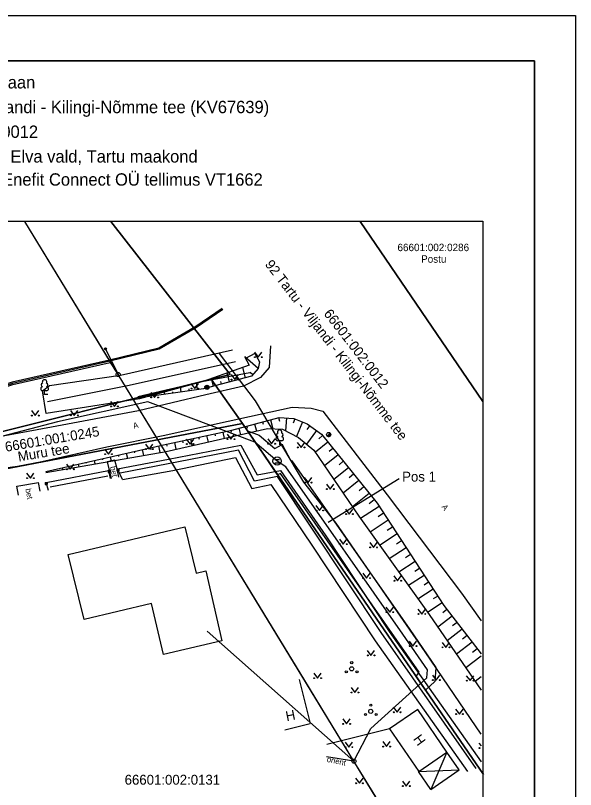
# Model space of a CAD drawing. Extents: x 627624 to 627729, y 6468528 to 6468676.
# Drawn here: x 627660.6 to 627728.6, y 6468582.3 to 6468676.3 of the extents above; entities that cross this region are included whole.
import ezdxf

# ---------------------------------------------------------------- set-up
doc = ezdxf.new("R2010")
doc.units = 0
for name, color, linetype in [('AED', 7, 'Continuous'), ('HALJASTUS', 7, 'Continuous'), ('HOONE', 7, 'Continuous'), ('Hoone Elu- või ühiskondlik hoone', 7, 'Continuous'), ('HOONEDET', 7, 'Continuous'), ('KASUTUSALA', 7, 'Continuous'), ('KPKAABEL', 7, 'Continuous'), ('MPKAABEL', 7, 'Continuous'), ('MPOHULIIN', 7, 'Continuous'), ('PIIR', 7, 'Continuous'), ('POST', 7, 'Continuous'), ('PR_SIDE', 7, 'Continuous'), ('proj_trass_kliendiliin ohuliin', 7, 'Continuous'), ('proj_trass_multitoru ohuliinil', 7, 'Continuous'), ('PUU', 7, 'Continuous'), ('RAJATIS', 7, 'Continuous'), ('RELJEEF', 7, 'Continuous'), ('SITRASS', 7, 'Continuous'), ('TEE', 7, 'Continuous'), ('VORMISTUS', 7, 'Continuous')]:
    doc.layers.add(name, color=color, linetype=linetype)

msp = doc.modelspace()

# ---------------------------------------------------------------- linework, layer by layer
at = {"layer": 'AED'}
for p, q in [((627671.829, 6468621.099), (627671.829, 6468620.849)), ((627671.829, 6468621.099), (627672.079, 6468621.099)), ((627671.829, 6468620.849), (627672.079, 6468620.849)), ((627672.079, 6468621.099), (627672.079, 6468620.849)), ((627672.91, 6468621.284), (627672.91, 6468621.034)), ((627672.91, 6468621.284), (627673.16, 6468621.284)), ((627672.91, 6468621.034), (627673.16, 6468621.034)), ((627673.16, 6468621.284), (627673.16, 6468621.034)), ((627664.186, 6468619.637), (627664.186, 6468619.387)), ((627664.186, 6468619.637), (627664.436, 6468619.637)), ((627664.436, 6468619.637), (627664.436, 6468619.387)), ((627664.186, 6468619.387), (627664.436, 6468619.387)), ((627706.037, 6468589.677), (627698.423, 6468587.794))]:
    msp.add_line(p, q, dxfattribs=at)
at = {"layer": 'HALJASTUS'}
for p, q in [((627689.619, 6468635.444), (627690.082, 6468634.837)), ((627690.082, 6468634.837), (627690.528, 6468635.444)), ((627686.777, 6468632.723), (627687.24, 6468632.116)), ((627687.24, 6468632.116), (627687.686, 6468632.723)), ((627681.896, 6468631.637), (627682.36, 6468631.031)), ((627682.36, 6468631.031), (627682.805, 6468631.637)), ((627677.016, 6468630.552), (627677.479, 6468629.945)), ((627677.479, 6468629.945), (627677.925, 6468630.552)), ((627672.135, 6468629.466), (627672.598, 6468628.86)), ((627672.598, 6468628.86), (627673.044, 6468629.466)), ((627662.515, 6468628.343), (627662.979, 6468627.737)), ((627662.979, 6468627.737), (627663.424, 6468628.343)), ((627667.254, 6468628.381), (627667.717, 6468627.774)), ((627667.717, 6468627.774), (627668.163, 6468628.381)), ((627686.303, 6468625.491), (627686.767, 6468624.885)), ((627686.767, 6468624.885), (627687.212, 6468625.491)), ((627676.376, 6468624.287), (627676.84, 6468623.68)), ((627676.84, 6468623.68), (627677.285, 6468624.287)), ((627681.34, 6468624.889), (627681.803, 6468624.282)), ((627681.803, 6468624.282), (627682.249, 6468624.889)), ((627691.237, 6468624.939), (627691.701, 6468624.332)), ((627691.701, 6468624.332), (627692.146, 6468624.939)), ((627694.818, 6468624.487), (627695.282, 6468623.88)), ((627695.282, 6468623.88), (627695.727, 6468624.487)), ((627671.416, 6468623.671), (627671.88, 6468623.064)), ((627671.88, 6468623.064), (627672.325, 6468623.671)), ((627666.768, 6468621.827), (627667.232, 6468621.22)), ((627667.232, 6468621.22), (627667.677, 6468621.827)), ((627661.927, 6468620.755), (627662.391, 6468620.148)), ((627662.391, 6468620.148), (627662.836, 6468620.755)), ((627664.781, 6468619.103), (627671.798, 6468620.423)), ((627695.682, 6468620.217), (627696.146, 6468619.61)), ((627696.146, 6468619.61), (627696.591, 6468620.217)), ((627698.368, 6468619.424), (627698.831, 6468618.817)), ((627698.831, 6468618.817), (627699.277, 6468619.424)), ((627697.083, 6468616.826), (627697.547, 6468616.219)), ((627697.547, 6468616.219), (627697.992, 6468616.826)), ((627700.689, 6468616.392), (627701.153, 6468615.785)), ((627701.153, 6468615.785), (627701.598, 6468616.392)), ((627699.95, 6468612.729), (627700.413, 6468612.123)), ((627700.413, 6468612.123), (627700.859, 6468612.729)), ((627703.625, 6468612.345), (627704.088, 6468611.738)), ((627704.088, 6468611.738), (627704.534, 6468612.345)), ((627702.774, 6468608.603), (627703.237, 6468607.996)), ((627703.237, 6468607.996), (627703.683, 6468608.603)), ((627706.56, 6468608.297), (627707.024, 6468607.69)), ((627707.024, 6468607.69), (627707.469, 6468608.297)), ((627705.598, 6468604.477), (627706.061, 6468603.87)), ((627706.061, 6468603.87), (627706.507, 6468604.477)), ((627709.496, 6468604.249), (627709.959, 6468603.643)), ((627709.959, 6468603.643), (627710.405, 6468604.249)), ((627708.421, 6468600.351), (627708.885, 6468599.744)), ((627708.885, 6468599.744), (627709.33, 6468600.351)), ((627712.431, 6468600.202), (627712.895, 6468599.595)), ((627712.895, 6468599.595), (627713.34, 6468600.202)), ((627703.321, 6468599.226), (627703.784, 6468598.619)), ((627703.784, 6468598.619), (627704.23, 6468599.226)), ((627696.823, 6468596.463), (627697.286, 6468595.856)), ((627697.286, 6468595.856), (627697.732, 6468596.463)), ((627711.245, 6468596.224), (627711.709, 6468595.618)), ((627711.709, 6468595.618), (627712.154, 6468596.224)), ((627715.367, 6468596.154), (627715.83, 6468595.548)), ((627715.83, 6468595.548), (627716.276, 6468596.154)), ((627701.368, 6468594.711), (627701.831, 6468594.104)), ((627701.831, 6468594.104), (627702.277, 6468594.711)), ((627706.485, 6468592.319), (627706.949, 6468591.712)), ((627706.949, 6468591.712), (627707.394, 6468592.319)), ((627714.069, 6468592.098), (627714.533, 6468591.491)), ((627714.533, 6468591.491), (627714.978, 6468592.098)), ((627700.358, 6468590.904), (627700.821, 6468590.297)), ((627700.821, 6468590.297), (627701.267, 6468590.904)), ((627700.627, 6468588.074), (627701.091, 6468587.467)), ((627701.091, 6468587.467), (627701.536, 6468588.074)), ((627705.206, 6468588.141), (627705.669, 6468587.534)), ((627705.669, 6468587.534), (627706.115, 6468588.141)), ((627716.893, 6468587.972), (627717.167, 6468587.613)), ((627701.907, 6468583.694), (627702.37, 6468583.087)), ((627702.37, 6468583.087), (627702.816, 6468583.694)), ((627707.596, 6468583.357), (627708.06, 6468582.75)), ((627708.06, 6468582.75), (627708.505, 6468583.357))]:
    msp.add_line(p, q, dxfattribs=at)
for points in [[(627664.314, 6468627.994), (627663.863, 6468630.771), (627664.725, 6468631.383), (627673.353, 6468632.664), (627686.946, 6468635.712)], [(627664.47, 6468629.471), (627674.392, 6468631.453), (627687.331, 6468634.332)], [(627689.052, 6468632.927), (627683.236, 6468631.825), (627675.654, 6468629.762), (627664.314, 6468627.994)], [(627673.61, 6468619.969), (627672.976, 6468621.286), (627679.187, 6468622.456), (627687.969, 6468624.157), (627689.948, 6468620.551), (627692.796, 6468621.064), (627698.292, 6468613.159), (627705.989, 6468601.538), (627717.166, 6468585.678)], [(627716.572, 6468584.873), (627705.028, 6468601.396), (627692.406, 6468620.356), (627689.621, 6468619.759), (627687.703, 6468623.543), (627673.321, 6468620.739)], [(627673.61, 6468619.969), (627679.701, 6468621.092), (627687.315, 6468622.642), (627689.297, 6468618.889), (627691.61, 6468619.392), (627696.609, 6468612.017), (627704.309, 6468600.39), (627715.503, 6468584.506)], [(627664.609, 6468618.629), (627664.298, 6468619.611), (627671.869, 6468621.074), (627672.073, 6468620.112)]]:
    msp.add_lwpolyline(points, dxfattribs=at)
for centre in [(627689.681, 6468634.837), (627690.51, 6468634.837), (627686.839, 6468632.116), (627687.668, 6468632.116), (627681.959, 6468631.031), (627682.787, 6468631.031), (627677.078, 6468629.945), (627677.907, 6468629.945), (627672.197, 6468628.86), (627673.026, 6468628.86), (627662.578, 6468627.737), (627663.407, 6468627.737), (627667.316, 6468627.774), (627668.145, 6468627.774), (627681.402, 6468624.282), (627682.231, 6468624.282), (627686.366, 6468624.885), (627687.195, 6468624.885), (627691.3, 6468624.332), (627692.129, 6468624.332), (627676.439, 6468623.68), (627677.267, 6468623.68), (627694.881, 6468623.88), (627695.709, 6468623.88), (627671.479, 6468623.064), (627672.307, 6468623.064), (627666.831, 6468621.22), (627667.66, 6468621.22), (627661.99, 6468620.148), (627662.819, 6468620.148), (627695.745, 6468619.61), (627696.573, 6468619.61), (627698.43, 6468618.817), (627699.259, 6468618.817), (627697.146, 6468616.219), (627697.975, 6468616.219), (627700.752, 6468615.785), (627701.58, 6468615.785), (627700.012, 6468612.123), (627700.841, 6468612.123), (627703.687, 6468611.738), (627704.516, 6468611.738), (627702.836, 6468607.996), (627703.665, 6468607.996), (627706.623, 6468607.69), (627707.451, 6468607.69), (627705.66, 6468603.87), (627706.489, 6468603.87), (627709.558, 6468603.643), (627710.387, 6468603.643), (627708.484, 6468599.744), (627709.313, 6468599.744), (627712.494, 6468599.595), (627713.323, 6468599.595), (627703.383, 6468598.619), (627704.212, 6468598.619), (627696.885, 6468595.856), (627697.714, 6468595.856), (627711.308, 6468595.618), (627712.137, 6468595.618), (627715.429, 6468595.548), (627716.258, 6468595.548), (627701.43, 6468594.104), (627702.259, 6468594.104), (627706.548, 6468591.712), (627707.377, 6468591.712), (627714.132, 6468591.491), (627714.96, 6468591.491), (627700.42, 6468590.297), (627701.249, 6468590.297), (627705.268, 6468587.534), (627706.097, 6468587.534), (627700.69, 6468587.467), (627701.518, 6468587.467), (627716.955, 6468587.365), (627701.969, 6468583.087), (627702.798, 6468583.087), (627707.659, 6468582.75), (627708.488, 6468582.75)]:
    msp.add_circle(centre, 0.055, dxfattribs=at)
at = {"layer": 'HOONE'}
for p, q in [((627695.051, 6468595.673), (627696.376, 6468590.356)), ((627693.298, 6468589.589), (627696.386, 6468590.358)), ((627714.488, 6468584.702), (627713.001, 6468586.862)), ((627711.065, 6468582.328), (627709.57, 6468584.502)), ((627711.065, 6468582.328), (627714.488, 6468584.702))]:
    msp.add_line(p, q, dxfattribs=at)
msp.add_lwpolyline([(627706.037, 6468589.677), (627709.589, 6468584.515), (627713.017, 6468586.873), (627709.466, 6468592.035)], close=True, dxfattribs=at)
at = {"layer": 'Hoone Elu- või ühiskondlik hoone'}
msp.add_lwpolyline([(627678.585, 6468598.716), (627677.114, 6468604.925), (627668.925, 6468602.995), (627666.971, 6468610.855), (627681.171, 6468614.225), (627682.555, 6468608.606), (627683.705, 6468608.876), (627685.675, 6468600.395)], close=True, dxfattribs=at)
at = {"layer": 'HOONEDET'}
for p, q in [((627713.001, 6468586.862), (627711.065, 6468582.328)), ((627709.57, 6468584.502), (627714.488, 6468584.702))]:
    msp.add_line(p, q, dxfattribs=at)
at = {"layer": 'KASUTUSALA'}
msp.add_lwpolyline([(627688.77, 6468625.91), (627690.186, 6468625.375), (627692.094, 6468623.767), (627693.002, 6468624.248), (627694.016, 6468622.332), (627694.153, 6468622.241), (627708.491, 6468601.771), (627711.663, 6468597.152), (627711.557, 6468595.436), (627710.406, 6468594.398), (627709.264, 6468596.061), (627709.624, 6468596.588), (627692.769, 6468620.73), (627692.444, 6468620.559), (627690.735, 6468623.048)], close=True, dxfattribs=at)
at = {"layer": 'KPKAABEL'}
msp.add_lwpolyline([(627685.782, 6468640.643), (627682.599, 6468638.441), (627678.043, 6468635.809), (627672.046, 6468634.344), (627660.214, 6468631.662), (627657.997, 6468630.954), (627658.117, 6468626.708), (627657.689, 6468626.13), (627652.495, 6468625.008), (627640.455, 6468623.259), (627634.742, 6468622.776)], dxfattribs=at)
at = {"layer": 'MPKAABEL'}
msp.add_line((627701.716, 6468585.772), (627698.369, 6468586.307), dxfattribs=at)
for points in [[(627685.699, 6468640.768), (627682.519, 6468638.568), (627677.987, 6468635.95), (627672.012, 6468634.49), (627660.175, 6468631.807), (627657.844, 6468631.063), (627657.966, 6468626.756), (627657.602, 6468626.265), (627652.468, 6468625.156), (627640.438, 6468623.408), (627634.759, 6468622.928)], [(627634.732, 6468622.624), (627640.472, 6468623.11), (627652.522, 6468624.86), (627657.776, 6468625.995), (627658.268, 6468626.66), (627658.15, 6468630.845), (627660.253, 6468631.517), (627672.08, 6468634.198), (627673.058, 6468632.736)]]:
    msp.add_lwpolyline(points, dxfattribs=at)
at = {"layer": 'MPOHULIIN'}
for points in [[(627672.71, 6468633.307), (627661.72, 6468651.3)], [(627679.915, 6468621.5), (627673.058, 6468632.736), (627672.71, 6468633.307)], [(627695.728, 6468595.585), (627679.915, 6468621.5)], [(627704.355, 6468581.436), (627701.716, 6468585.772), (627695.728, 6468595.585)]]:
    msp.add_lwpolyline(points, dxfattribs=at)
at = {"layer": 'PIIR'}
for points in [[(627672.184, 6468651.3), (627686.69, 6468632.75), (627684.35, 6468632.16), (627652.69, 6468624.22), (627634.665, 6468622.433)], [(627717.444, 6468584.146), (627688.18, 6468626.77), (627684.35, 6468632.16), (627686.69, 6468632.75), (627672.184, 6468651.3)], [(627717.373, 6468629.447), (627702.473, 6468651.3)], [(627702.473, 6468651.3), (627717.373, 6468629.447)], [(627634.665, 6468622.433), (627652.69, 6468624.22), (627684.35, 6468632.16), (627688.18, 6468626.77), (627643.52, 6468618.24), (627634.7, 6468617.952)], [(627660.121, 6468546.6), (627653, 6468577.43), (627643.52, 6468618.24), (627688.18, 6468626.77), (627717.444, 6468584.146)]]:
    msp.add_lwpolyline(points, dxfattribs=at)
at = {"layer": 'POST'}
msp.add_line((627698.467, 6468625.263), (627698.821, 6468625.617), dxfattribs=at)
msp.add_lwpolyline([(627671.521, 6468635.845), (627673.058, 6468632.736)], dxfattribs=at)
for centre, radius in [((627671.521, 6468635.845), 0.125), ((627671.521, 6468635.845), 0.105), ((627671.521, 6468635.845), 0.0851), ((627671.521, 6468635.845), 0.0651), ((627671.521, 6468635.845), 0.0451), ((627671.521, 6468635.845), 0.0251), ((627671.521, 6468635.845), 0.00511), ((627673.058, 6468632.736), 0.25), ((627698.644, 6468625.44), 0.25), ((627701.716, 6468585.772), 0.25), ((627701.716, 6468585.772), 0.0234)]:
    msp.add_circle(centre, radius, dxfattribs=at)
for radius, start, end in [(0.225, 224.85406, 45.03563), (0.2, 224.84272, 45.04698), (0.175, 224.82813, 45.06157), (0.15, 224.80867, 45.08103), (0.125, 224.78144, 45.10826), (0.1, 224.74058, 45.14911), (0.075, 224.67249, 45.2172), (0.05, 224.53632, 45.35338), (0.025, 224.12776, 45.76193)]:
    msp.add_arc((627698.644, 6468625.44), radius, start, end, dxfattribs=at)
at = {"layer": 'PR_SIDE'}
for p, q in [((627692.087, 6468622.42), (627692.668, 6468622.42)), ((627692.087, 6468622.02), (627692.668, 6468622.02))]:
    msp.add_line(p, q, dxfattribs=at)
msp.add_lwpolyline([(627701.716, 6468585.772), (627703.748, 6468589.737), (627710.584, 6468595.905), (627710.644, 6468596.87), (627707.669, 6468601.201), (627693.442, 6468621.512), (627692.377, 6468622.22), (627689.672, 6468624.5), (627676.659, 6468629.413), (627665.71, 6468626.997), (627653.138, 6468623.704), (627643.511, 6468622.305), (627640.257, 6468622.059), (627634.674, 6468621.524), (627633.255, 6468621.458)], dxfattribs=at)
msp.add_circle((627692.377, 6468622.22), 0.5, dxfattribs=at)
at = {"layer": 'proj_trass_kliendiliin ohuliin'}
msp.add_lwpolyline([(627701.716, 6468585.772), (627683.873, 6468601.563)], dxfattribs=at)
at = {"layer": 'proj_trass_multitoru ohuliinil'}
msp.add_lwpolyline([(627717.167, 6468560.389), (627701.716, 6468585.772), (627673.058, 6468632.736), (627661.72, 6468651.3)], dxfattribs=at)
at = {"layer": 'PUU'}
for p, q in [((627664.363, 6468630.767), (627663.883, 6468630.767)), ((627664.123, 6468630.292), (627664.123, 6468630.767)), ((627664.503, 6468630.292), (627664.123, 6468630.292)), ((627692.934, 6468624.685), (627692.454, 6468624.685)), ((627692.693, 6468624.21), (627692.693, 6468624.685)), ((627693.074, 6468624.21), (627692.693, 6468624.21))]:
    msp.add_line(p, q, dxfattribs=at)
for centre, radius in [((627701.438, 6468596.982), 0.25), ((627701.438, 6468597.732), 0.125), ((627700.788, 6468596.607), 0.125), ((627702.088, 6468596.607), 0.125), ((627703.756, 6468592.571), 0.125), ((627703.106, 6468591.446), 0.125), ((627703.756, 6468591.821), 0.25), ((627704.406, 6468591.446), 0.125)]:
    msp.add_circle(centre, radius, dxfattribs=at)
for centre, radius, start, end in [((627664.123, 6468631.812), 0.277, 332.5799, 207.4201), ((627663.885, 6468631.005), 0.238, 90.0016, 269.3953), ((627663.953, 6468631.465), 0.233, 109.02174, 253.14154), ((627664.293, 6468631.465), 0.233, 286.85082, 70.98591), ((627664.36, 6468631.005), 0.238, 270.6047, 89.9984), ((627692.523, 6468625.382), 0.233, 109.02174, 253.14154), ((627692.693, 6468625.73), 0.277, 332.5799, 207.4201), ((627692.864, 6468625.382), 0.233, 286.85082, 70.98591), ((627692.456, 6468624.922), 0.238, 90.0016, 269.3953), ((627692.931, 6468624.922), 0.238, 270.6047, 89.9984)]:
    msp.add_arc(centre, radius, start, end, dxfattribs=at)
at = {"layer": 'RAJATIS'}
for radius in [0.25, 0.225, 0.2, 0.175, 0.15, 0.125, 0.1, 0.075, 0.05, 0.025]:
    msp.add_circle((627683.853, 6468631.183), radius, dxfattribs=at)
at = {"layer": 'RELJEEF'}
for p, q in [((627690.075, 6468633.453), (627688.458, 6468634.878)), ((627689.682, 6468635.294), (627688.556, 6468634.689)), ((627686.583, 6468631.828), (627686.299, 6468632.92)), ((627688.519, 6468632.333), (627688.192, 6468633.586)), ((627689.414, 6468632.703), (627689.095, 6468632.984)), ((627684.648, 6468631.324), (627684.405, 6468632.254)), ((627685.616, 6468631.576), (627685.537, 6468631.879)), ((627687.551, 6468632.081), (627687.459, 6468632.432)), ((627680.716, 6468630.621), (627680.627, 6468631.243)), ((627681.706, 6468630.762), (627681.675, 6468630.976)), ((627682.696, 6468630.903), (627682.581, 6468631.707)), ((627683.68, 6468631.071), (627683.614, 6468631.326)), ((627675.766, 6468629.917), (627675.759, 6468629.967)), ((627676.756, 6468630.058), (627676.719, 6468630.314)), ((627677.746, 6468630.199), (627677.731, 6468630.303)), ((627678.736, 6468630.34), (627678.673, 6468630.779)), ((627679.726, 6468630.48), (627679.703, 6468630.64)), ((627691.575, 6468627.246), (627691.875, 6468626.138)), ((627692.54, 6468627.507), (627692.655, 6468627.083)), ((627693.535, 6468627.461), (627693.415, 6468625.887)), ((627694.522, 6468627.344), (627694.324, 6468626.837)), ((627687.714, 6468626.201), (627687.924, 6468625.425)), ((627688.679, 6468626.462), (627688.745, 6468626.218)), ((627689.644, 6468626.724), (627689.876, 6468625.867)), ((627690.61, 6468626.985), (627690.683, 6468626.716)), ((627695.453, 6468626.979), (627694.753, 6468625.193)), ((627696.337, 6468626.526), (627695.986, 6468626.044)), ((627683.813, 6468625.322), (627683.981, 6468624.533)), ((627684.791, 6468625.53), (627684.84, 6468625.297)), ((627685.769, 6468625.739), (627685.931, 6468624.974)), ((627686.747, 6468625.947), (627686.795, 6468625.721)), ((627697.146, 6468625.939), (627695.948, 6468624.289)), ((627697.912, 6468625.306), (627697.428, 6468624.916)), ((627678.922, 6468624.282), (627678.977, 6468624.026)), ((627679.9, 6468624.49), (627680.079, 6468623.65)), ((627680.878, 6468624.698), (627680.931, 6468624.45)), ((627681.856, 6468624.906), (627682.03, 6468624.092)), ((627682.835, 6468625.114), (627682.886, 6468624.874)), ((627698.539, 6468624.527), (627697.024, 6468623.307)), ((627675.02, 6468623.402), (627675.065, 6468623.202)), ((627675.995, 6468623.623), (627676.158, 6468622.907)), ((627676.971, 6468623.844), (627677.023, 6468623.614)), ((627677.946, 6468624.066), (627678.131, 6468623.249)), ((627699.166, 6468623.748), (627698.692, 6468623.367)), ((627671.119, 6468622.517), (627671.151, 6468622.378)), ((627672.094, 6468622.738), (627672.211, 6468622.223)), ((627673.07, 6468622.96), (627673.108, 6468622.79)), ((627674.045, 6468623.181), (627674.185, 6468622.565)), ((627699.794, 6468622.969), (627698.149, 6468621.645)), ((627666.243, 6468621.411), (627666.291, 6468621.198)), ((627667.218, 6468621.633), (627667.236, 6468621.553)), ((627668.194, 6468621.854), (627668.265, 6468621.54)), ((627669.169, 6468622.075), (627669.194, 6468621.966)), ((627670.144, 6468622.296), (627670.238, 6468621.882)), ((627701.048, 6468621.412), (627699.274, 6468619.984)), ((627700.421, 6468622.19), (627699.908, 6468621.778)), ((627664.293, 6468620.969), (627664.318, 6468620.856)), ((627665.268, 6468621.19), (627665.279, 6468621.141)), ((627701.675, 6468620.633), (627701.123, 6468620.189)), ((627702.302, 6468619.854), (627700.399, 6468618.322)), ((627702.929, 6468619.075), (627702.339, 6468618.6)), ((627703.556, 6468618.296), (627701.524, 6468616.66)), ((627704.773, 6468616.711), (627702.506, 6468615.228)), ((627704.183, 6468617.517), (627703.554, 6468617.011)), ((627705.32, 6468615.874), (627704.65, 6468615.436)), ((627705.868, 6468615.037), (627703.67, 6468613.6)), ((627706.415, 6468614.2), (627705.766, 6468613.776)), ((627706.962, 6468613.363), (627704.834, 6468611.972)), ((627707.509, 6468612.526), (627706.881, 6468612.115)), ((627708.057, 6468611.689), (627705.998, 6468610.343)), ((627708.604, 6468610.852), (627707.997, 6468610.455)), ((627709.151, 6468610.015), (627707.163, 6468608.715)), ((627710.246, 6468608.341), (627708.327, 6468607.087)), ((627709.698, 6468609.178), (627709.112, 6468608.795)), ((627710.793, 6468607.504), (627710.228, 6468607.135)), ((627711.34, 6468606.667), (627709.491, 6468605.458)), ((627711.887, 6468605.83), (627711.343, 6468605.474)), ((627712.435, 6468604.993), (627710.655, 6468603.83)), ((627713.02, 6468604.183), (627712.511, 6468603.79)), ((627713.631, 6468603.392), (627711.891, 6468602.049)), ((627714.853, 6468601.808), (627713.029, 6468600.401)), ((627714.242, 6468602.6), (627713.707, 6468602.188)), ((627715.464, 6468601.016), (627714.904, 6468600.585)), ((627716.074, 6468600.225), (627714.166, 6468598.753)), ((627716.685, 6468599.433), (627716.1, 6468598.982)), ((627717.167, 6468598.542), (627715.304, 6468597.104)), ((627717.167, 6468596.016), (627716.442, 6468595.456))]:
    msp.add_line(p, q, dxfattribs=at)
for points in [[(627689.682, 6468635.294), (627690.235, 6468634.267), (627690.092, 6468633.472), (627689.259, 6468632.526), (627683.446, 6468631.01), (627675.445, 6468629.871)], [(627688.429, 6468634.933), (627688.985, 6468633.865), (627683.41, 6468631.904), (627675.465, 6468630.016)], [(627664.293, 6468620.969), (627678.559, 6468624.205), (627686.866, 6468625.972), (627692.626, 6468627.53), (627694.391, 6468627.395), (627696.02, 6468626.757), (627697.766, 6468625.488), (627704.517, 6468617.101), (627712.652, 6468604.661), (627717.167, 6468598.808)], [(627664.284, 6468620.85), (627678.877, 6468623.378), (627691.199, 6468626.166), (627693.024, 6468626.089), (627694.96, 6468625.086), (627696.853, 6468623.559), (627702.288, 6468615.532), (627710.843, 6468603.567), (627717.167, 6468594.405)]]:
    msp.add_lwpolyline(points, dxfattribs=at)
at = {"layer": 'SITRASS'}
msp.add_lwpolyline([(627717.167, 6468589.049), (627713.907, 6468593.848), (627710.374, 6468599.048), (627699.564, 6468614.681), (627695.628, 6468619.665), (627689.767, 6468629.543), (627685.369, 6468635.281)], dxfattribs=at)
at = {"layer": 'TEE'}
for p, q in [((627663.568, 6468618.555), (627663.372, 6468619.631)), ((627660.951, 6468618.078), (627660.755, 6468619.153))]:
    msp.add_line(p, q, dxfattribs=at)
for points in [[(627691.556, 6468636.216), (627691.411, 6468633.572), (627690.377, 6468632.362), (627688.302, 6468631.311), (627683.705, 6468630.285), (627675.534, 6468628.326), (627664.963, 6468626.349), (627655.323, 6468624.553), (627656.855, 6468621.064), (627660.849, 6468621.603), (627663.795, 6468622.181), (627671.677, 6468623.939), (627678.512, 6468625.342), (627686.437, 6468627.071), (627694.212, 6468628.779), (627696.498, 6468628.635), (627697.947, 6468628.287), (627705.762, 6468618.126), (627714.785, 6468606.184), (627717.167, 6468602.8)], [(627673.157, 6468620.276), (627672.925, 6468621.283), (627672.671, 6468622.34), (627671.739, 6468622.144), (627671.964, 6468621.133), (627672.206, 6468620.091)], [(627660.755, 6468619.153), (627663.372, 6468619.631)]]:
    msp.add_lwpolyline(points, dxfattribs=at)
at = {"layer": 'VORMISTUS'}
msp.add_line((627698.597, 6468614.818), (627707.223, 6468620.117), dxfattribs=at)
for points in [[(627623.638, 6468676.344), (627728.638, 6468676.344), (627728.638, 6468527.844), (627623.638, 6468527.844)], [(627628.638, 6468533.344), (627723.638, 6468533.344), (627723.638, 6468670.844), (627628.638, 6468670.844)], [(627628.638, 6468670.844), (627723.638, 6468670.844), (627723.638, 6468533.344), (627628.638, 6468533.344)], [(627717.388, 6468546.344), (627634.888, 6468546.344), (627634.888, 6468651.344), (627717.388, 6468651.344)]]:
    msp.add_lwpolyline(points, close=True, dxfattribs=at)

# ---------------------------------------------------------------- texts
at = {"layer": 'HOONE'}
for rotation, p in [(11.20898, (627693.541, 6468590.621)), (306.15917, (627708.852, 6468588.456))]:
    msp.add_text('H', height=1.2, rotation=rotation, dxfattribs=at).set_placement(p)
at = {"layer": 'MPKAABEL'}
msp.add_text('orient', height=0.7, rotation=347.92105, dxfattribs=at).set_placement((627698.368, 6468585.691))
at = {"layer": 'PIIR'}
for s, height, p in [('66601:002:0286', 0.9, (627707.005, 6468647.718)), ('Postu', 0.9, (627709.876, 6468646.309)), ('66601:002:0131', 1.2, (627673.85, 6468582.912))]:
    msp.add_text(s, height=height, dxfattribs=at).set_placement(p)
for s, rotation, p in [('92 Tartu - Viljandi - Kilingi-Nõmme tee', 307.62986, (627690.837, 6468646.091)), ('66601:002:0012', 307.62986, (627697.977, 6468640.107)), ('66601:001:0245', 9.56292, (627659.419, 6468623.341)), ('Muru tee', 9.56292, (627660.979, 6468622.152))]:
    msp.add_text(s, height=1.2, rotation=rotation, dxfattribs=at).set_placement(p)
at = {"layer": 'TEE'}
for s, rotation, p in [('A', 14.14709, (627674.964, 6468626.151)), ('bet', 281.74812, (627672.078, 6468621.523)), ('bet', 281.74812, (627661.781, 6468618.812)), ('A', 304.09221, (627712.328, 6468616.655))]:
    msp.add_text(s, height=0.7, rotation=rotation, dxfattribs=at).set_placement(p)
at = {"layer": 'VORMISTUS'}
for s, height, p in [('Isikliku kasutusõiguse ala plaan', 1.5, (627634.893, 6468667.478)), ('Kinnistu nimi: 92 Tartu - Viljandi - Kilingi-Nõmme tee (KV67639)', 1.5, (627634.893, 6468664.478)), ('Katastritunnus: 66601:002:0012', 1.5, (627634.893, 6468661.478)), ('Pos 1', 1.2, (627707.571, 6468619.729))]:
    msp.add_text(s, height=height, dxfattribs=at).set_placement(p)
for s, p in [('Asukoht: Väike-Rakke küla, Elva vald, Tartu maakond', (627634.893, 6468658.478)), ('Kirjanurk OÜ töö nr 8727P/Enefit Connect OÜ tellimus VT1662', (627634.886, 6468655.673))]:
    msp.add_text(s, height=1.5, rotation=360, dxfattribs=at).set_placement(p)

doc.saveas('drawing.dxf')
